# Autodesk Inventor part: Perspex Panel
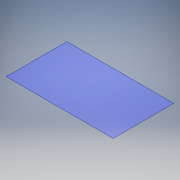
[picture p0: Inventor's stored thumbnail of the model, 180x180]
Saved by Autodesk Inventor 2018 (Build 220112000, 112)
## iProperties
Created: 2020-10
Part Number: Perspex Panel
Material: Polycarbonate, Clear
Document SubType Name: Modeling
Designer: cadcr
Density: 1.2 g/cm^3
Appearance: Clear - Blue
Author: cadcr
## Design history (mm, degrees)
sketch "Sketch1"
  geometry: L1 (-925, -525)-(925, -525); L2 (925, -525)-(925, 525); L3 (925, 525)-(-925, 525); L4 (-925, 525)-(-925, -525); L5 (-925, -525)-(925, 525); L6 (925, -525)-(-925, 525); 1 further point
  constraints: 12 end point, 2 midpoint, 2 parallel, 1 horizontal, 1 perpendicular
  dimensions: "d0" = 1850 distance of L2.end L3.end; "d1" = 1050 distance of L3.end L1.start
extrude "Extrusion1" new body sketch "Sketch1" distance "d2" = 3; taper "d3" = 0 deg
body "Solid1"
